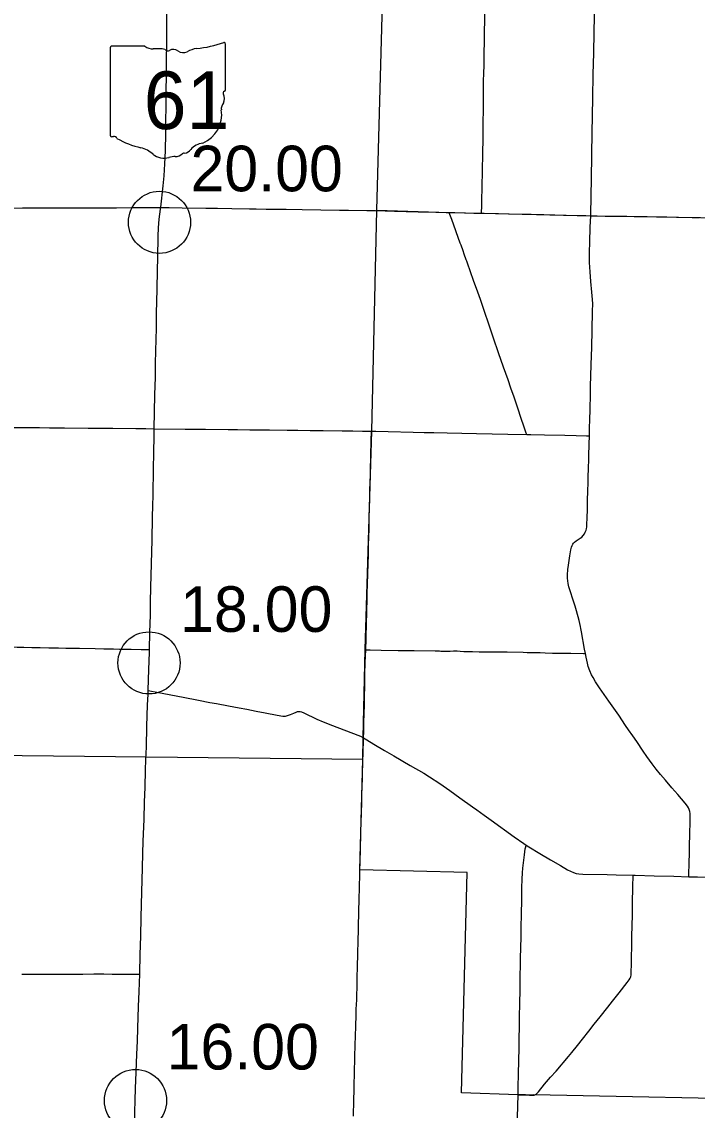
# Model space of a CAD drawing. Extents: x 9078 to 9739, y 4248 to 4966.
# Drawn here: x 9378.4 to 9460, y 4699.7 to 4831.1 of the extents above; entities that cross this region are included whole.
import ezdxf

# ---------------------------------------------------------------- set-up
doc = ezdxf.new("R2010")
doc.units = 0
for name, color, linetype in [('Default', 7, 'Continuous'), ('GM_X_County_Road', 7, 'Continuous'), ('GM_X_State_Route', 7, 'Continuous'), ('GM_X_State_Shield', 7, 'Continuous'), ('GM_X_Township', 7, 'Continuous'), ('GM_X_Township_Road', 7, 'Continuous')]:
    doc.layers.add(name, color=color, linetype=linetype)

msp = doc.modelspace()

# ---------------------------------------------------------------- linework, layer by layer
at = {"layer": 'Default'}
for centre in [(9395.01, 4806.89), (9393.75, 4753.68), (9392.12, 4700.83)]:
    msp.add_circle(centre, 3.75, dxfattribs=at)
at = {"layer": 'GM_X_County_Road'}
for points in [[(9447.12, 4807.69), (9447.17, 4810.2), (9447.2, 4812.01), (9447.26, 4815.13), (9447.3, 4817.67), (9447.38, 4821.94), (9447.42, 4824.73), (9447.47, 4827.35), (9447.51, 4829.81), (9447.55, 4831.78), (9447.59, 4833.67), (9447.6, 4834.25)], [(9368.54, 4808.62), (9369.62, 4808.62), (9370.85, 4808.62), (9372, 4808.63), (9373.64, 4808.61), (9375.2, 4808.61), (9376.76, 4808.61), (9378.48, 4808.62), (9381.02, 4808.63), (9382.41, 4808.63), (9384.3, 4808.63), (9385.7, 4808.63), (9387.66, 4808.64), (9389.8, 4808.65), (9391.85, 4808.66), (9393.65, 4808.66), (9394.72, 4808.66), (9395.15, 4808.67)], [(9395.15, 4808.67), (9395.32, 4808.68), (9396.19, 4808.67), (9397.75, 4808.64), (9400.62, 4808.6), (9402.01, 4808.59), (9403.74, 4808.56), (9405.87, 4808.52), (9406.69, 4808.51), (9407.92, 4808.49), (9409.07, 4808.47), (9410.3, 4808.46), (9412.26, 4808.43), (9416.78, 4808.36), (9417.84, 4808.35), (9420.06, 4808.32), (9420.76, 4808.31)], [(9420.76, 4808.31), (9421.12, 4808.31), (9423.42, 4808.25), (9424.81, 4808.2), (9426.28, 4808.16), (9427.35, 4808.14), (9428.42, 4808.11), (9429.65, 4808.08), (9430.01, 4808.08)], [(9430.01, 4808.08), (9430.71, 4808.06), (9433.01, 4807.99), (9433.92, 4807.98)], [(9433.92, 4807.98), (9434.24, 4807.98), (9435.96, 4807.95), (9437.19, 4807.91), (9438.83, 4807.88), (9439.9, 4807.86), (9441.45, 4807.83), (9444.16, 4807.77), (9446.13, 4807.71), (9446.53, 4807.7), (9447.12, 4807.69)], [(9446.95, 4781.12), (9446.98, 4782.14), (9447, 4782.96), (9447.03, 4784.35), (9447.07, 4786.07), (9447.1, 4787.06), (9447.16, 4789.68), (9447.23, 4791.81), (9447.29, 4793.86), (9447.34, 4796.16), (9447.35, 4797.06), (9447.33, 4797.55), (9447.26, 4798.45), (9447.14, 4799.75), (9447.06, 4800.9), (9446.98, 4802.04), (9446.96, 4802.7), (9446.97, 4803.27), (9447.01, 4804.5), (9447.06, 4806.31), (9447.12, 4807.69)], [(9447.12, 4807.69), (9447.88, 4807.66), (9448.86, 4807.65), (9449.92, 4807.64), (9451.48, 4807.62), (9452.38, 4807.6), (9453.94, 4807.58), (9456.32, 4807.54), (9457.46, 4807.51), (9459.35, 4807.48), (9460.25, 4807.46)], [(9445.93, 4757.82), (9445.88, 4758.08), (9445.71, 4758.8), (9445.39, 4759.98), (9445.22, 4760.53), (9444.95, 4761.39), (9444.68, 4762.25), (9444.48, 4762.88), (9444.39, 4763.28), (9444.34, 4763.6), (9444.31, 4763.92), (9444.32, 4764.33), (9444.36, 4764.98), (9444.42, 4765.47), (9444.59, 4766.6), (9444.73, 4767.33), (9444.79, 4767.65), (9444.88, 4767.88), (9444.95, 4768.02), (9445.05, 4768.15), (9445.17, 4768.27), (9445.36, 4768.42), (9445.84, 4768.73), (9446.03, 4768.88), (9446.2, 4769.06), (9446.35, 4769.25), (9446.46, 4769.47), (9446.55, 4769.7), (9446.59, 4769.86), (9446.63, 4770.1), (9446.66, 4770.51), (9446.68, 4771.08), (9446.71, 4772.31), (9446.73, 4773.13), (9446.77, 4774.61), (9446.79, 4775.26), (9446.81, 4776.08), (9446.85, 4777.23), (9446.87, 4778.21), (9446.88, 4778.7), (9446.93, 4780.09), (9446.95, 4781.12)], [(9446.48, 4754.83), (9446.38, 4755.34), (9446.01, 4757.44), (9445.93, 4757.82)], [(9458.96, 4727.86), (9458.97, 4728.12), (9459.01, 4729.51), (9459.04, 4730.74), (9459.05, 4731.48), (9459.06, 4731.97), (9459.07, 4732.62), (9459.1, 4733.44), (9459.11, 4734.09), (9459.13, 4735.16), (9459.12, 4735.49), (9459.09, 4735.73), (9459.02, 4735.97), (9458.92, 4736.19), (9458.79, 4736.4), (9458.54, 4736.73), (9457.63, 4737.78), (9456.93, 4738.59), (9456.13, 4739.51), (9455.54, 4740.2), (9455.01, 4740.83), (9454.52, 4741.48), (9453.91, 4742.36), (9453.45, 4743.04), (9452.67, 4744.19), (9452.21, 4744.87), (9451.69, 4745.61), (9451.32, 4746.14), (9450.49, 4747.36), (9449.32, 4749.05), (9448.19, 4750.66), (9447.69, 4751.41), (9447.39, 4751.9), (9447.2, 4752.26), (9447, 4752.71), (9446.81, 4753.25), (9446.71, 4753.65), (9446.56, 4754.37), (9446.48, 4754.83)], [(9393.64, 4750.36), (9393.86, 4750.32), (9395.55, 4749.99), (9397.89, 4749.54), (9399.74, 4749.18), (9401.11, 4748.92), (9401.92, 4748.77), (9403.37, 4748.5), (9404.66, 4748.25), (9405.55, 4748.08), (9406.68, 4747.87), (9407.8, 4747.65), (9409.25, 4747.37), (9409.9, 4747.25), (9410.06, 4747.24), (9410.23, 4747.26), (9410.46, 4747.32), (9410.85, 4747.45), (9411.23, 4747.61), (9411.53, 4747.75), (9411.69, 4747.8), (9411.85, 4747.82), (9412.01, 4747.81), (9412.17, 4747.77), (9412.47, 4747.64), (9414.02, 4746.89), (9414.78, 4746.58), (9415.93, 4746.13), (9418.14, 4745.27), (9419.29, 4744.83), (9419.59, 4744.69), (9419.67, 4744.64)], [(9419.6, 4742.12), (9419.61, 4742.51), (9419.62, 4742.92), (9419.64, 4743.39), (9419.65, 4743.91), (9419.67, 4744.64)], [(9419.67, 4744.64), (9420.08, 4744.39), (9420.92, 4743.88), (9422.19, 4743.12), (9423.32, 4742.45), (9425.31, 4741.3), (9426.95, 4740.36), (9427.65, 4739.93), (9428.87, 4739.11), (9430.08, 4738.26), (9431.28, 4737.4), (9432.82, 4736.31), (9433.36, 4735.93), (9434.22, 4735.31), (9435.08, 4734.68), (9437.88, 4732.67), (9439.02, 4731.86), (9439.3, 4731.68)], [(9419.2, 4727.7), (9419.2, 4727.72), (9419.22, 4728.21), (9419.23, 4728.67), (9419.23, 4729.01), (9419.24, 4729.31), (9419.24, 4729.5), (9419.25, 4729.8), (9419.26, 4730.05), (9419.27, 4730.34), (9419.28, 4730.56), (9419.29, 4730.8), (9419.29, 4731.18), (9419.29, 4731.43), (9419.31, 4731.91), (9419.32, 4732.37), (9419.32, 4732.59), (9419.35, 4733.5), (9419.38, 4734.23), (9419.39, 4734.64), (9419.41, 4735.3), (9419.43, 4735.87), (9419.45, 4736.53), (9419.46, 4737.1), (9419.48, 4737.92), (9419.5, 4738.58), (9419.54, 4739.89), (9419.56, 4740.68), (9419.58, 4741.28), (9419.59, 4741.78), (9419.6, 4742.12)], [(9438.33, 4701.52), (9438.36, 4702.47), (9438.39, 4704.02), (9438.42, 4705.66), (9438.45, 4707.14), (9438.46, 4708.37), (9438.49, 4709.68), (9438.51, 4710.92), (9438.54, 4712.56), (9438.57, 4714.2), (9438.59, 4716), (9438.61, 4717.07), (9438.64, 4717.97), (9438.69, 4720.6), (9438.72, 4721.83), (9438.74, 4723.22), (9438.79, 4725.19), (9438.81, 4726.5), (9438.83, 4727.57), (9438.86, 4728.31), (9438.92, 4728.88), (9439.12, 4730.51), (9439.21, 4731.24), (9439.26, 4731.48), (9439.3, 4731.68)], [(9439.3, 4731.68), (9439.64, 4731.46), (9440.97, 4730.65), (9442.24, 4729.9), (9443.45, 4729.2), (9444.3, 4728.71), (9444.67, 4728.52), (9445.04, 4728.36), (9445.36, 4728.26), (9445.68, 4728.21), (9446.17, 4728.17), (9449.12, 4728.11), (9450.19, 4728.08), (9452.26, 4728.04)], [(9418.45, 4698.96), (9418.47, 4699.7), (9418.48, 4700.11), (9418.5, 4701.01), (9418.52, 4701.99), (9418.55, 4703.06), (9418.57, 4703.79), (9418.58, 4704.53), (9418.61, 4705.68), (9418.63, 4706.34), (9418.66, 4707.32), (9418.66, 4707.65), (9418.67, 4707.92), (9418.68, 4708.24), (9418.69, 4708.57), (9418.7, 4708.88), (9418.72, 4709.53), (9418.74, 4710.11), (9418.76, 4710.84), (9418.78, 4711.5), (9418.79, 4711.91), (9418.81, 4712.4), (9418.84, 4713.05), (9418.85, 4713.54), (9418.88, 4714.52), (9418.89, 4715.1), (9418.9, 4715.51), (9418.91, 4716.08), (9418.92, 4716.57), (9418.93, 4716.9), (9418.94, 4717.39), (9418.96, 4718.13), (9418.97, 4718.62), (9419.01, 4720.09), (9419.04, 4721.49), (9419.06, 4722.06), (9419.09, 4723.37), (9419.11, 4724.03), (9419.13, 4724.77), (9419.15, 4725.58), (9419.17, 4726.08), (9419.17, 4726.57), (9419.18, 4727.06), (9419.2, 4727.7)], [(9440.48, 4701.58), (9440.51, 4701.6), (9440.63, 4701.71), (9440.79, 4701.9), (9441.52, 4702.79), (9442.27, 4703.66), (9442.93, 4704.39), (9444.43, 4706.13), (9444.85, 4706.63), (9445.51, 4707.48), (9446.12, 4708.25), (9446.87, 4709.22), (9447.54, 4710.05), (9448.26, 4710.95), (9449.17, 4712.11), (9449.73, 4712.82), (9450.54, 4713.85), (9451.52, 4715.07), (9451.77, 4715.4), (9451.89, 4715.61), (9451.94, 4715.76), (9451.99, 4716), (9452.01, 4716.33), (9452.03, 4717.32), (9452.05, 4718.05), (9452.07, 4719.53), (9452.1, 4720.68), (9452.15, 4723.22), (9452.17, 4724.37), (9452.22, 4726.92), (9452.25, 4727.74), (9452.26, 4728.04)], [(9452.26, 4728.04), (9452.49, 4728.04), (9454.78, 4727.97), (9457.16, 4727.91), (9458.96, 4727.86)], [(9458.96, 4727.86), (9460.03, 4727.83), (9463.64, 4727.76), (9464.38, 4727.74), (9466.76, 4727.67), (9468.65, 4727.62), (9471.11, 4727.56), (9472.17, 4727.54), (9472.46, 4727.53)], [(9438.07, 4688.37), (9438.07, 4688.61), (9438.1, 4690.65), (9438.15, 4693.27), (9438.17, 4694.66), (9438.2, 4696.13), (9438.33, 4701.52)], [(9438.33, 4701.52), (9438.57, 4701.52), (9438.9, 4701.53), (9439.72, 4701.49), (9440.13, 4701.48), (9440.29, 4701.5), (9440.37, 4701.52), (9440.44, 4701.56), (9440.48, 4701.58)]]:
    msp.add_lwpolyline(points, dxfattribs=at)
at = {"layer": 'GM_X_State_Route'}
for points in [[(9395.78, 4817.65), (9395.78, 4817.82), (9395.82, 4822.17), (9395.85, 4825.2), (9395.89, 4829.8), (9395.94, 4835.39)], [(9395.16, 4808.7), (9395.44, 4811.28), (9395.56, 4812.5), (9395.67, 4813.97), (9395.74, 4815.53), (9395.78, 4817.65)], [(9392, 4698.01), (9392.13, 4702.27), (9392.2, 4704.24), (9392.28, 4706.45), (9392.34, 4708.01), (9392.39, 4709.56), (9392.49, 4712.18), (9392.56, 4713.99), (9392.63, 4716.11), (9392.63, 4716.2), (9392.69, 4718.41), (9392.75, 4720.71), (9392.81, 4722.92), (9392.89, 4726.04), (9392.97, 4728.91), (9393.02, 4730.71), (9393.06, 4732.1), (9393.15, 4734.81), (9393.21, 4736.86), (9393.27, 4738.66), (9393.34, 4740.71), (9393.38, 4742.02), (9393.38, 4742.05), (9393.43, 4743.5), (9393.5, 4746.04), (9393.58, 4748.58), (9393.63, 4749.89), (9393.64, 4750.36), (9393.69, 4751.69), (9393.72, 4752.84), (9393.79, 4754.97), (9393.8, 4755.29), (9393.85, 4757.35), (9393.91, 4759.48), (9393.94, 4761.03), (9393.98, 4762.84), (9394.11, 4768.5), (9394.18, 4771.28), (9394.19, 4772.68), (9394.23, 4773.91), (9394.29, 4777.19), (9394.32, 4778.99), (9394.37, 4781.2), (9394.39, 4781.96), (9394.43, 4783.99), (9394.47, 4786.04), (9394.52, 4788.17), (9394.55, 4789.89), (9394.61, 4792.76), (9394.64, 4794.08), (9394.67, 4795.88), (9394.73, 4798.83), (9394.77, 4801.13), (9394.8, 4802.6), (9394.86, 4805.23), (9394.9, 4806.21), (9394.99, 4807.27), (9395.13, 4808.46), (9395.15, 4808.67), (9395.16, 4808.7)]]:
    msp.add_lwpolyline(points, dxfattribs=at)
at = {"layer": 'GM_X_State_Shield'}
for p, q in [((9393.26, 4828.16), (9389.19, 4828.16)), ((9402.97, 4822.89), (9402.97, 4828.42)), ((9389.05, 4827.98), (9389.05, 4817.41)), ((9402.97, 4822.89), (9402.97, 4822.89))]:
    msp.add_line(p, q, dxfattribs=at)
for centre, radius, start, end in [((9389.21, 4828), 0.161, 98.1301, 188.1301), ((9394.23, 4829.38), 1.56, 231.6195, 271.1119), ((9398.01, 4842.56), 14.76, 275.8445, 288.9065), ((9402.82, 4828.44), 0.155, 351.8621, 97.738), ((9394.75, 4822.23), 5.62, 80.4867, 94.9883), ((9396.03, 4828.05), 0.451, 219.7921, 297.1024), ((9396.69, 4826.83), 0.938, 54.4667, 119.1411), ((9397.9, 4828.51), 1.13, 233.8562, 294.8282), ((9399.89, 4824.93), 2.97, 97.3462, 120.7689), ((9402.81, 4822.87), 0.166, 289.6038, 7.7341), ((9402.93, 4822.49), 0.24, 107.944, 210.337), ((9401.41, 4821.79), 1.44, 340.033, 23.6496), ((9398.84, 4819.88), 3.69, 292.3089, 8.9858), ((9403.53, 4820.58), 1.05, 136.8065, 186.9296), ((9389.21, 4817.39), 0.163, 171.9584, 258.3066), ((9389.23, 4818.47), 1.24, 267.339, 280.6039), ((9389.49, 4816.8), 0.448, 29.7484, 93.2717), ((9395.14, 4826.29), 10.66, 240.4129, 257.1985), ((9400.4, 4814.44), 2.02, 94.4031, 142.5768), ((9391.96, 4812.66), 3.34, 47.1842, 75.836), ((9395.57, 4816.75), 2.12, 230.7004, 286.2918), ((9396.95, 4815.96), 1.13, 268.777, 315.5493), ((9397.97, 4814.93), 0.318, 65.7517, 132.6484), ((9397.83, 4816.39), 1.19, 282.8732, 323.2771), ((9396.79, 4813.09), 1.74, 85.6951, 111.2099)]:
    msp.add_arc(centre, radius, start, end, dxfattribs=at)
at = {"layer": 'GM_X_Township'}
for points in [[(9421.27, 4808.36), (9421.98, 4834.78), (9422.27, 4847.94), (9422.45, 4861.29), (9422.93, 4886.35), (9423.7, 4914.12), (9424.44, 4940.55)], [(9472, 4700.88), (9440.23, 4701.51), (9439.88, 4701.49), (9439.24, 4701.54), (9438.32, 4701.53), (9431.5, 4701.75), (9432.2, 4728.37), (9419.23, 4728.71), (9419.57, 4742.03), (9419.64, 4744.65), (9419.88, 4755.3), (9420.65, 4781.66), (9421.27, 4808.36), (9430.03, 4808.09), (9433.94, 4807.99), (9447.11, 4807.68), (9473.64, 4807.27)], [(9419.57, 4742.03), (9393.43, 4742.31), (9367.13, 4742.58), (9341.32, 4742.67), (9341.61, 4751.46)]]:
    msp.add_lwpolyline(points, dxfattribs=at)
at = {"layer": 'GM_X_Township_Road'}
for points in [[(9433.92, 4807.98), (9433.93, 4808.13), (9433.94, 4808.78), (9433.97, 4809.76), (9433.98, 4810.91), (9434.03, 4813.37), (9434.06, 4814.92), (9434.1, 4817.3), (9434.13, 4819.26), (9434.15, 4820.16), (9434.14, 4823.48), (9434.16, 4824.06), (9434.21, 4824.78), (9434.24, 4825.93), (9434.26, 4827.49), (9434.28, 4828.55), (9434.3, 4829.61), (9434.33, 4831.58), (9434.35, 4832.56), (9434.36, 4833.55), (9434.37, 4834.12), (9434.36, 4834.52)], [(9432.13, 4802.19), (9432.07, 4802.36), (9431.82, 4803.06), (9431.69, 4803.45), (9431.45, 4804.14), (9431.36, 4804.37), (9430.33, 4807.23), (9430.1, 4807.85), (9430.01, 4808.08)], [(9437.46, 4786.88), (9437.12, 4787.86), (9436.57, 4789.41), (9435.97, 4791.12), (9435.37, 4792.91), (9434.77, 4794.7), (9434.31, 4796.01), (9433.78, 4797.57), (9433.31, 4798.88), (9433, 4799.73), (9432.53, 4801.05), (9432.26, 4801.82), (9432.13, 4802.19)], [(9439.38, 4781.27), (9439.33, 4781.42), (9439.03, 4782.27), (9438.71, 4783.2), (9438.29, 4784.44), (9437.85, 4785.77), (9437.46, 4786.88)], [(9367.92, 4782.21), (9368.04, 4782.21), (9369.51, 4782.19), (9370.66, 4782.19), (9371.48, 4782.17), (9373.28, 4782.16), (9375.25, 4782.13), (9376.81, 4782.13), (9378.12, 4782.12), (9379.43, 4782.11), (9380.5, 4782.1), (9381.73, 4782.07), (9383.53, 4782.07), (9386.4, 4782.05), (9389.36, 4782.02), (9392.15, 4781.99), (9393.38, 4781.98), (9394.36, 4781.96), (9394.39, 4781.96)], [(9394.39, 4781.96), (9398.13, 4781.92), (9399.36, 4781.91), (9400.59, 4781.89), (9403.3, 4781.86), (9404.45, 4781.85), (9405.92, 4781.83), (9406.42, 4781.83), (9407.32, 4781.82), (9408.3, 4781.81), (9410.43, 4781.78), (9411.74, 4781.77), (9413.22, 4781.75), (9413.96, 4781.74), (9414.78, 4781.73), (9417.07, 4781.7), (9418.38, 4781.69), (9419.53, 4781.67), (9420.11, 4781.66), (9420.62, 4781.66)], [(9420.14, 4763.06), (9420.15, 4763.23), (9420.17, 4764.38), (9420.22, 4765.69), (9420.25, 4766.67), (9420.28, 4767.82), (9420.31, 4768.97), (9420.33, 4769.7), (9420.35, 4770.6), (9420.36, 4771.34), (9420.38, 4772.41), (9420.41, 4773.47), (9420.44, 4774.37), (9420.48, 4775.68), (9420.5, 4776.25), (9420.52, 4776.99), (9420.56, 4778.55), (9420.6, 4780.68), (9420.62, 4781.5), (9420.62, 4781.66)], [(9420.62, 4781.66), (9421.17, 4781.65), (9422.65, 4781.62), (9425.68, 4781.54), (9426.99, 4781.52), (9428.14, 4781.5), (9429.78, 4781.47), (9433.31, 4781.39), (9437.08, 4781.31), (9439.38, 4781.27)], [(9439.38, 4781.27), (9439.87, 4781.25), (9441.51, 4781.24), (9443.97, 4781.19), (9445.36, 4781.16), (9446.59, 4781.12), (9446.95, 4781.12)], [(9419.93, 4755.28), (9419.97, 4756.6), (9419.98, 4757.17), (9420.01, 4758.07), (9420.06, 4760.12), (9420.1, 4761.19), (9420.12, 4762.17), (9420.14, 4763.06)], [(9367.52, 4755.77), (9367.89, 4755.77), (9370.43, 4755.73), (9371.91, 4755.72), (9373.06, 4755.7), (9374.62, 4755.68), (9375.35, 4755.66), (9376.09, 4755.64), (9377.81, 4755.59), (9378.63, 4755.57), (9379.61, 4755.55), (9380.6, 4755.53), (9381.66, 4755.51), (9382.81, 4755.49), (9383.71, 4755.47), (9385.35, 4755.45), (9387.24, 4755.41), (9388.3, 4755.39), (9389.45, 4755.37), (9390.19, 4755.36), (9391.58, 4755.33), (9392.81, 4755.31), (9393.63, 4755.29), (9393.8, 4755.29)], [(9419.67, 4744.64), (9419.69, 4745.38), (9419.72, 4746.53), (9419.77, 4748.58), (9419.8, 4749.81), (9419.81, 4750.62), (9419.82, 4751.36), (9419.83, 4752.34), (9419.88, 4753.74), (9419.93, 4755.28)], [(9419.93, 4755.28), (9420.22, 4755.27), (9420.47, 4755.26), (9421.78, 4755.24), (9423.83, 4755.2), (9425.8, 4755.17), (9428.34, 4755.13), (9428.83, 4755.12), (9429, 4755.11), (9429.81, 4755.1), (9430.14, 4755.11), (9430.55, 4755.12), (9430.96, 4755.12), (9431.36, 4755.09), (9431.77, 4755.07), (9432.09, 4755.06), (9432.83, 4755.04), (9433.65, 4755.03), (9434.55, 4755.02), (9435.12, 4755.02), (9435.78, 4755.01), (9436.35, 4755.01), (9437.01, 4755), (9438.97, 4754.96), (9439.43, 4754.95)], [(9439.43, 4754.95), (9440.36, 4754.93), (9441.01, 4754.92), (9441.59, 4754.9), (9442.48, 4754.87), (9443.14, 4754.87), (9444.7, 4754.85), (9446.25, 4754.83), (9446.48, 4754.83)], [(9378.37, 4716.11), (9379.11, 4716.1), (9380.09, 4716.11), (9380.91, 4716.11), (9381.65, 4716.11), (9382.47, 4716.11), (9383.7, 4716.11), (9385.1, 4716.11), (9385.75, 4716.11), (9387.07, 4716.12), (9387.89, 4716.12), (9388.3, 4716.12), (9389.28, 4716.11), (9390.59, 4716.11), (9391.74, 4716.11), (9392.15, 4716.11), (9392.55, 4716.11), (9392.63, 4716.11)]]:
    msp.add_lwpolyline(points, dxfattribs=at)

# ---------------------------------------------------------------- texts
at = {"layer": 'Default'}
for s, p in [('20.00', (9398.76, 4810.64)), ('18.00', (9397.5, 4757.43)), ('16.00', (9395.87, 4704.58))]:
    msp.add_text(s, height=5.5, dxfattribs=at).set_placement(p)
at = {"layer": 'GM_X_State_Shield'}
msp.add_text('61', height=6.961, dxfattribs=at).set_placement((9393.1, 4818.15))

doc.saveas('drawing.dxf')
